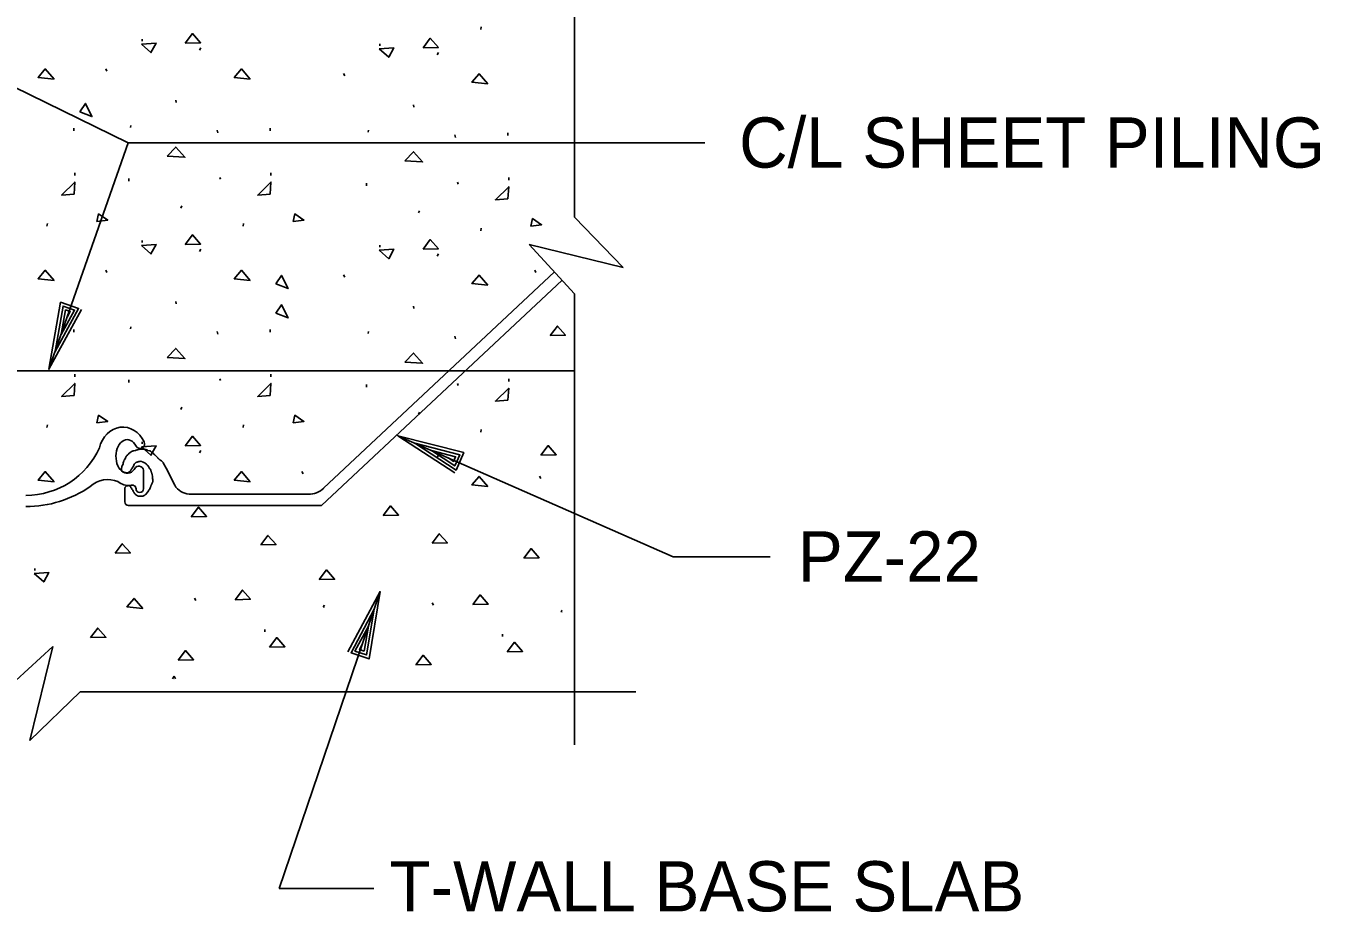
# Model space of a CAD drawing. Extents: x 22369.6 to 22428.3, y 22369.6 to 22415.
# Drawn here: x 22384.482 to 22389.267, y 22374.698 to 22377.975 of the extents above; entities that cross this region are included whole.
import ezdxf

# ---------------------------------------------------------------- set-up
doc = ezdxf.new("R2010")
doc.units = 0
for name, color, linetype in [('Level 1', 7, 'Continuous'), ('Level 2', 7, 'Continuous'), ('Level 4', 7, 'Continuous'), ('Level 8', 7, 'Continuous')]:
    doc.layers.add(name, color=color, linetype=linetype)

msp = doc.modelspace()

# ---------------------------------------------------------------- linework, layer by layer
at = {"layer": 'Level 1'}
for p, q in [((22386.5109, 22377.2675), (22386.5109, 22379.7606)), ((22384.8608, 22377.5434), (22384.0344, 22377.9463)), ((22384.5676, 22376.7059), (22384.8608, 22377.5434)), ((22384.8608, 22377.5434), (22386.9925, 22377.5434)), ((22384.6631, 22377.4226), (22384.6631, 22377.4318)), ((22384.5602, 22377.2348), (22384.5617, 22377.2444)), ((22386.6908, 22377.0817), (22386.5109, 22377.2675)), ((22386.5109, 22376.984), (22386.3432, 22377.1673)), ((22386.3432, 22377.1673), (22386.6908, 22377.0817)), ((22386.5109, 22375.3165), (22386.5109, 22376.984)), ((22384.6597, 22376.8431), (22384.6597, 22376.8531)), ((22384.5904, 22376.771), (22384.5904, 22376.771)), ((22384.5676, 22376.7059), (22384.5676, 22376.7059)), ((22383.6419, 22376.6994), (22386.5109, 22376.6994)), ((22384.6631, 22376.6781), (22384.6631, 22376.6874)), ((22385.9339, 22376.5397), (22385.9376, 22376.5475)), ((22384.9119, 22376.4299), (22384.9126, 22376.4372)), ((22385.857, 22376.46), (22386.8753, 22376.0124)), ((22385.857, 22376.46), (22385.857, 22376.46)), ((22385.9203, 22376.4322), (22385.9203, 22376.4322)), ((22385.1237, 22376.3967), (22385.1286, 22376.405)), ((22386.0024, 22376.3792), (22386.0074, 22376.3875)), ((22385.5072, 22376.3191), (22385.5027, 22376.3279)), ((22386.8753, 22376.0124), (22387.2338, 22376.0124)), ((22385.7919, 22375.8837), (22385.419, 22374.7862)), ((22385.7919, 22375.8837), (22385.7919, 22375.8837)), ((22385.7697, 22375.8182), (22385.7697, 22375.8182)), ((22384.3989, 22375.513), (22384.5822, 22375.6807)), ((22384.5822, 22375.6807), (22384.4967, 22375.3331)), ((22384.4967, 22375.3331), (22384.6824, 22375.513)), ((22386.7371, 22375.513), (22384.6824, 22375.513)), ((22385.419, 22374.7862), (22385.7687, 22374.7862))]:
    msp.add_line(p, q, dxfattribs=at)
msp.add_lwpolyline([(22384.7447, 22377.2522), (22384.785, 22377.2574), (22384.7512, 22377.2801)], close=True, dxfattribs=at)
for points in [[(22384.6884, 22376.9265), (22384.5676, 22376.7059), (22384.6107, 22376.9537), (22384.6771, 22376.9304), (22384.5904, 22376.771), (22384.6198, 22376.9393), (22384.6623, 22376.9244), (22384.6123, 22376.8336), (22384.6288, 22376.9249), (22384.6463, 22376.9187), (22384.6351, 22376.8987)], [(22386.0681, 22376.3222), (22385.857, 22376.46), (22386.1013, 22376.3977), (22386.0729, 22376.3331), (22385.9203, 22376.4322), (22386.0862, 22376.3898), (22386.068, 22376.3484), (22385.9812, 22376.4054), (22386.0711, 22376.3819), (22386.0636, 22376.3648), (22386.0445, 22376.3776)], [(22385.6729, 22375.6614), (22385.7919, 22375.8837), (22385.7509, 22375.6349), (22385.6842, 22375.6576), (22385.7697, 22375.8182), (22385.7418, 22375.6493), (22385.6989, 22375.6638), (22385.7483, 22375.7552), (22385.7326, 22375.6636), (22385.715, 22375.6696), (22385.726, 22375.6897)], [(22386.4644, 22375.8153), (22386.4598, 22375.8098)], [(22386.4598, 22375.8098), (22386.4647, 22375.8093)]]:
    msp.add_lwpolyline(points, dxfattribs=at)
at = {"layer": 'Level 2'}
for p, q in [((22385.5826, 22376.2656), (22386.4365, 22377.0654)), ((22385.5754, 22376.2019), (22386.4645, 22377.0347)), ((22384.917, 22376.3336), (22384.917, 22376.2638)), ((22385.001, 22376.3405), (22385.0323, 22376.2768)), ((22384.8482, 22376.2155), (22384.8481, 22376.2601)), ((22384.8894, 22376.2634), (22384.8894, 22376.2638)), ((22385.5263, 22376.2434), (22385.0859, 22376.2434)), ((22384.8603, 22376.2019), (22385.5754, 22376.2019))]:
    msp.add_line(p, q, dxfattribs=at)
for points in [[(22384.8683, 22376.3287), (22384.8671, 22376.3276), (22384.8645, 22376.3259), (22384.8638, 22376.3259), (22384.8617, 22376.3238), (22384.8599, 22376.3233), (22384.8594, 22376.3228), (22384.8562, 22376.3226), (22384.855, 22376.3226), (22384.8535, 22376.3229), (22384.8526, 22376.3229), (22384.8511, 22376.3233), (22384.8501, 22376.3231), (22384.8492, 22376.3234), (22384.8484, 22376.3236), (22384.8466, 22376.3244), (22384.8444, 22376.3249), (22384.8433, 22376.3254), (22384.8426, 22376.3259), (22384.8418, 22376.3267), (22384.8386, 22376.3286), (22384.8375, 22376.3291), (22384.8371, 22376.3299), (22384.8361, 22376.3307), (22384.8356, 22376.3321), (22384.8355, 22376.3349), (22384.8358, 22376.3382), (22384.836, 22376.3413), (22384.8365, 22376.3427), (22384.8368, 22376.3442), (22384.8373, 22376.3457), (22384.8373, 22376.3475), (22384.8401, 22376.3528), (22384.8413, 22376.3558), (22384.8413, 22376.3568), (22384.8418, 22376.3584), (22384.8419, 22376.3594), (22384.8436, 22376.3634), (22384.8446, 22376.3664), (22384.8461, 22376.3704), (22384.8467, 22376.3712), (22384.8482, 22376.3727), (22384.8501, 22376.3763), (22384.8507, 22376.3783), (22384.8519, 22376.381), (22384.8531, 22376.383), (22384.8534, 22376.3836), (22384.8539, 22376.3848), (22384.8545, 22376.3858), (22384.856, 22376.3871), (22384.8582, 22376.3886), (22384.8589, 22376.3893), (22384.86, 22376.3901), (22384.8607, 22376.3911), (22384.8612, 22376.3914), (22384.8625, 22376.3936), (22384.8645, 22376.3951), (22384.8668, 22376.3961), (22384.8671, 22376.3967), (22384.8731, 22376.401), (22384.8768, 22376.4025), (22384.8784, 22376.4035), (22384.8802, 22376.404), (22384.8817, 22376.4045), (22384.8864, 22376.4053), (22384.8884, 22376.4057), (22384.8905, 22376.4063), (22384.8932, 22376.4077), (22384.8955, 22376.408), (22384.8983, 22376.409), (22384.9006, 22376.409), (22384.9098, 22376.4097), (22384.9121, 22376.4103), (22384.9154, 22376.4105), (22384.9174, 22376.4103), (22384.9202, 22376.4097), (22384.924, 22376.4095), (22384.926, 22376.409), (22384.9287, 22376.4075), (22384.9305, 22376.4068), (22384.9326, 22376.4063), (22384.9335, 22376.4057), (22384.9393, 22376.4039), (22384.9406, 22376.4035), (22384.9431, 22376.4024), (22384.9466, 22376.3996)], [(22384.9466, 22376.3996), (22384.9494, 22376.3976), (22384.9514, 22376.3961), (22384.9526, 22376.3944), (22384.9552, 22376.3924), (22384.9569, 22376.3904), (22384.958, 22376.3898), (22384.9585, 22376.3893), (22384.9607, 22376.3881), (22384.9618, 22376.3868), (22384.9622, 22376.3859), (22384.964, 22376.384), (22384.965, 22376.3825), (22384.9698, 22376.378), (22384.9701, 22376.3765), (22384.9725, 22376.375), (22384.9733, 22376.374), (22384.9774, 22376.3702), (22384.9807, 22376.3684), (22384.9842, 22376.3665), (22384.9849, 22376.3659), (22384.9861, 22376.3646), (22384.9872, 22376.3639), (22384.9889, 22376.3616), (22384.9892, 22376.3607), (22384.9895, 22376.3601), (22384.99, 22376.3591), (22384.99, 22376.3592), (22384.9902, 22376.3594), (22385.001, 22376.3405)], [(22384.9494, 22376.2841), (22384.9499, 22376.2853), (22384.9512, 22376.2913), (22384.9512, 22376.2924), (22384.9512, 22376.2936), (22384.9514, 22376.2952), (22384.9514, 22376.2976), (22384.9504, 22376.3017), (22384.9502, 22376.3032), (22384.9501, 22376.3037), (22384.9504, 22376.3045), (22384.9501, 22376.305), (22384.9504, 22376.3063), (22384.9502, 22376.3075), (22384.9506, 22376.3088), (22384.9502, 22376.3105), (22384.9487, 22376.3153), (22384.9474, 22376.3211), (22384.9471, 22376.3226), (22384.9464, 22376.3238), (22384.9461, 22376.3249), (22384.9461, 22376.3257), (22384.9456, 22376.3267), (22384.9452, 22376.3281), (22384.9451, 22376.3291), (22384.9446, 22376.3301), (22384.9444, 22376.3311), (22384.9436, 22376.3331), (22384.9433, 22376.3344), (22384.9426, 22376.336), (22384.9406, 22376.338), (22384.9393, 22376.3392), (22384.9381, 22376.3417), (22384.9356, 22376.346), (22384.9351, 22376.3471), (22384.9345, 22376.3478), (22384.9328, 22376.3503), (22384.9313, 22376.3516), (22384.9305, 22376.3519), (22384.93, 22376.3528), (22384.9287, 22376.3539), (22384.927, 22376.3561), (22384.9257, 22376.3573), (22384.925, 22376.3578), (22384.9244, 22376.3583), (22384.9237, 22376.3586), (22384.923, 22376.3589), (22384.922, 22376.3592), (22384.9196, 22376.3601), (22384.9181, 22376.3604), (22384.9156, 22376.3619), (22384.9116, 22376.3637), (22384.9106, 22376.3642), (22384.9061, 22376.3652), (22384.9043, 22376.3649), (22384.9031, 22376.3649), (22384.9015, 22376.3644), (22384.9003, 22376.3642), (22384.8993, 22376.3641), (22384.897, 22376.3637), (22384.8963, 22376.3637), (22384.894, 22376.3627), (22384.8927, 22376.3626), (22384.891, 22376.3619), (22384.8899, 22376.3609), (22384.889, 22376.3604), (22384.8879, 22376.3597), (22384.887, 22376.3591), (22384.8864, 22376.3581), (22384.8857, 22376.3578), (22384.8854, 22376.3571), (22384.8844, 22376.3564), (22384.8837, 22376.3558), (22384.8829, 22376.3548), (22384.8812, 22376.3513), (22384.8796, 22376.3475), (22384.8787, 22376.3461), (22384.8773, 22376.3438), (22384.8766, 22376.3423), (22384.8738, 22376.338), (22384.872, 22376.336), (22384.871, 22376.3335), (22384.8706, 22376.3329), (22384.8698, 22376.3319), (22384.8693, 22376.3304), (22384.8683, 22376.3287)], [(22384.8481, 22376.2601), (22384.8486, 22376.2609), (22384.8484, 22376.2624), (22384.8481, 22376.2624), (22384.8481, 22376.2636), (22384.8477, 22376.2654), (22384.8479, 22376.2659), (22384.8479, 22376.2657), (22384.8479, 22376.2664), (22384.8486, 22376.267), (22384.8489, 22376.2679), (22384.8499, 22376.2699), (22384.8499, 22376.2699), (22384.8517, 22376.272), (22384.8521, 22376.2722), (22384.8529, 22376.2732), (22384.8542, 22376.274), (22384.8554, 22376.2745), (22384.8582, 22376.275), (22384.8612, 22376.2753), (22384.8628, 22376.2753), (22384.8643, 22376.275), (22384.8676, 22376.2738), (22384.8685, 22376.2725), (22384.8686, 22376.271), (22384.8698, 22376.2697), (22384.8701, 22376.2684), (22384.8725, 22376.2664), (22384.8726, 22376.2659), (22384.8741, 22376.2626), (22384.8758, 22376.2602), (22384.8776, 22376.2583), (22384.8786, 22376.2551), (22384.8792, 22376.2541), (22384.8804, 22376.2521), (22384.8809, 22376.2515), (22384.8822, 22376.2486), (22384.8826, 22376.2481), (22384.8834, 22376.2476), (22384.8842, 22376.2466), (22384.887, 22376.2442), (22384.8872, 22376.2437), (22384.8879, 22376.243), (22384.8885, 22376.2418), (22384.8892, 22376.241), (22384.891, 22376.2397), (22384.8925, 22376.239), (22384.894, 22376.238), (22384.8962, 22376.2374), (22384.8972, 22376.2369), (22384.8983, 22376.2369), (22384.899, 22376.2365), (22384.9026, 22376.2362), (22384.9045, 22376.236), (22384.9088, 22376.2364), (22384.9098, 22376.2362), (22384.9114, 22376.2362), (22384.9151, 22376.237), (22384.9192, 22376.2387), (22384.92, 22376.2392), (22384.921, 22376.2397), (22384.922, 22376.2403), (22384.9234, 22376.2413), (22384.9245, 22376.242), (22384.9249, 22376.2427), (22384.9267, 22376.2443), (22384.9277, 22376.2457), (22384.9323, 22376.2508), (22384.9333, 22376.2523), (22384.9351, 22376.2556), (22384.9371, 22376.2588), (22384.9378, 22376.2596), (22384.9381, 22376.2606), (22384.939, 22376.2612), (22384.9403, 22376.2637), (22384.9419, 22376.2669), (22384.9429, 22376.269), (22384.9447, 22376.2743), (22384.9447, 22376.275), (22384.9452, 22376.2758), (22384.9456, 22376.2768), (22384.9461, 22376.2777), (22384.9472, 22376.2811), (22384.9479, 22376.2825), (22384.9494, 22376.2841)]]:
    msp.add_lwpolyline(points, dxfattribs=at)
for centre, radius, start, end in [((22384.9042, 22376.4298), 0.0171, 210.0864, 24.1441), ((22384.4823, 22376.5371), 0.2977, 270, 335.9098), ((22384.9001, 22376.3302), 0.0172, 348.5103, 135.7394), ((22384.7851, 22376.2049), 0.0931, 66.293, 134.0783), ((22384.863, 22376.3391), 0.0635, 230.4241, 276.2781), ((22384.8756, 22376.2634), 0.0138, 0.0038, 114.2261), ((22385.0932, 22376.3147), 0.0717, 211.905, 264.1589), ((22384.4823, 22376.6177), 0.4198, 270, 304.5362), ((22384.9032, 22376.2638), 0.0138, 180, 0), ((22385.5263, 22376.3263), 0.0829, 270, 313.4699), ((22384.8621, 22376.2156), 0.0138, 180.2909, 270.0528)]:
    msp.add_arc(centre, radius, start, end, dxfattribs=at)
for centre, major_axis, ratio, start_param, end_param in [((22384.8406, 22376.388), (0, 0.1036), 0.866676, 5.202938, 7.584426), ((22384.8566, 22376.3832), (0, 0.0622), 0.666679, 5.371054, 10.276478)]:
    msp.add_ellipse(centre, major_axis=major_axis, ratio=ratio, start_param=start_param, end_param=end_param, dxfattribs=at)
at = {"layer": 'Level 8'}
for p, q in [((22386.1641, 22377.9618), (22386.1656, 22377.9714)), ((22384.9119, 22377.9187), (22384.9126, 22377.926)), ((22385.7907, 22377.9012), (22385.7913, 22377.9085)), ((22385.1237, 22377.8856), (22385.1286, 22377.8939)), ((22386.0024, 22377.8681), (22386.0074, 22377.8764)), ((22384.782, 22377.808), (22384.7776, 22377.8167)), ((22385.6608, 22377.7905), (22385.6564, 22377.7992)), ((22385.0374, 22377.6924), (22385.0368, 22377.7005)), ((22385.9162, 22377.6749), (22385.9156, 22377.683)), ((22384.6597, 22377.5876), (22384.6597, 22377.5975)), ((22384.8688, 22377.5993), (22384.8701, 22377.6068)), ((22385.1918, 22377.5796), (22385.189, 22377.5895)), ((22385.3849, 22377.5876), (22385.3849, 22377.5975)), ((22385.7476, 22377.5818), (22385.7489, 22377.5893)), ((22386.0706, 22377.5621), (22386.0678, 22377.5721)), ((22386.2636, 22377.5701), (22386.2636, 22377.58)), ((22385.3883, 22377.4226), (22385.3883, 22377.4318)), ((22384.8626, 22377.4012), (22384.8626, 22377.4111)), ((22385.2018, 22377.408), (22385.1989, 22377.4151)), ((22385.7414, 22377.3837), (22385.7414, 22377.3936)), ((22386.0806, 22377.3905), (22386.0777, 22377.3976)), ((22386.2671, 22377.4051), (22386.2671, 22377.4143)), ((22385.0552, 22377.3017), (22385.0588, 22377.3095)), ((22385.9339, 22377.2842), (22385.9376, 22377.292)), ((22385.2854, 22377.2348), (22385.2868, 22377.2444)), ((22384.9119, 22377.1743), (22384.9126, 22377.1816)), ((22386.1641, 22377.2173), (22386.1656, 22377.227)), ((22385.1237, 22377.1411), (22385.1286, 22377.1494)), ((22385.7907, 22377.1568), (22385.7913, 22377.1641)), ((22386.0024, 22377.1236), (22386.0074, 22377.1319)), ((22384.782, 22377.0635), (22384.7776, 22377.0723)), ((22385.6608, 22377.046), (22385.6564, 22377.0548)), ((22386.3677, 22377.0635), (22386.3632, 22377.0723)), ((22385.0374, 22376.9479), (22385.0368, 22376.9561)), ((22385.9162, 22376.9304), (22385.9156, 22376.9386)), ((22384.8688, 22376.8549), (22384.8701, 22376.8624)), ((22385.3849, 22376.8431), (22385.3849, 22376.8531)), ((22385.1918, 22376.8352), (22385.189, 22376.8451)), ((22385.7476, 22376.8374), (22385.7489, 22376.8449)), ((22386.0706, 22376.8177), (22386.0678, 22376.8276)), ((22384.8626, 22376.6567), (22384.8626, 22376.6667)), ((22385.2018, 22376.6635), (22385.1989, 22376.6707)), ((22385.3883, 22376.6781), (22385.3883, 22376.6874)), ((22386.2671, 22376.6606), (22386.2671, 22376.6699)), ((22385.7414, 22376.6392), (22385.7414, 22376.6492)), ((22386.0806, 22376.646), (22386.0777, 22376.6532)), ((22385.0552, 22376.5572), (22385.0588, 22376.565)), ((22384.5602, 22376.4904), (22384.5617, 22376.5)), ((22385.2854, 22376.4904), (22385.2868, 22376.5)), ((22386.1641, 22376.4729), (22386.1656, 22376.4825)), ((22386.386, 22376.3016), (22386.3815, 22376.3104)), ((22384.5152, 22375.9615), (22384.5158, 22375.9688)), ((22385.1105, 22375.8507), (22385.106, 22375.8595)), ((22385.9893, 22375.8332), (22385.9848, 22375.842)), ((22385.3659, 22375.7351), (22385.3652, 22375.7432)), ((22386.2447, 22375.7176), (22386.244, 22375.7257))]:
    msp.add_line(p, q, dxfattribs=at)
for points in [[(22385.0716, 22377.9118), (22385.0983, 22377.9471), (22385.1283, 22377.9131)], [(22384.9094, 22377.908), (22384.9447, 22377.8764), (22384.9636, 22377.9118)], [(22385.9504, 22377.8943), (22385.9771, 22377.9296), (22386.0071, 22377.8956)], [(22385.7882, 22377.8905), (22385.8235, 22377.859), (22385.8424, 22377.8943)], [(22384.5865, 22377.7781), (22384.5537, 22377.8159), (22384.5273, 22377.7846)], [(22385.3117, 22377.7781), (22385.2789, 22377.8159), (22385.2525, 22377.7846)], [(22386.1905, 22377.7606), (22386.1577, 22377.7984), (22386.1313, 22377.7671)], [(22384.6812, 22377.6572), (22384.7265, 22377.6396), (22384.7026, 22377.6886)], [(22385.0049, 22377.4932), (22385.0364, 22377.5274), (22385.0703, 22377.4895)], [(22385.8837, 22377.4757), (22385.9152, 22377.5099), (22385.9491, 22377.4721)], [(22384.6607, 22377.3534), (22384.6631, 22377.3977), (22384.6141, 22377.3498)], [(22385.3858, 22377.3534), (22385.3883, 22377.3977), (22385.3392, 22377.3498)], [(22386.2646, 22377.3359), (22386.2671, 22377.3802), (22386.218, 22377.3323)], [(22385.4699, 22377.2522), (22385.5102, 22377.2574), (22385.4764, 22377.2801)], [(22386.3487, 22377.2347), (22386.389, 22377.2399), (22386.3552, 22377.2626)], [(22385.0716, 22377.1673), (22385.0983, 22377.2027), (22385.1283, 22377.1687)], [(22385.9504, 22377.1498), (22385.9771, 22377.1852), (22386.0071, 22377.1512)], [(22384.9094, 22377.1635), (22384.9447, 22377.132), (22384.9636, 22377.1673)], [(22385.7882, 22377.146), (22385.8235, 22377.1145), (22385.8424, 22377.1498)], [(22384.5865, 22377.0337), (22384.5537, 22377.0715), (22384.5273, 22377.0401)], [(22385.3117, 22377.0337), (22385.2789, 22377.0715), (22385.2525, 22377.0401)], [(22385.4064, 22377.0215), (22385.4517, 22377.0039), (22385.4278, 22377.0528)], [(22386.1905, 22377.0162), (22386.1577, 22377.054), (22386.1313, 22377.0226)], [(22385.4064, 22376.9128), (22385.4517, 22376.8952), (22385.4278, 22376.9441)], [(22386.4203, 22376.83), (22386.447, 22376.8653), (22386.477, 22376.8313)], [(22385.0049, 22376.7488), (22385.0364, 22376.7829), (22385.0703, 22376.7451)], [(22385.8837, 22376.7313), (22385.9152, 22376.7654), (22385.9491, 22376.7276)], [(22384.6607, 22376.609), (22384.6631, 22376.6532), (22384.6141, 22376.6053)], [(22385.3858, 22376.609), (22385.3883, 22376.6532), (22385.3392, 22376.6053)], [(22386.2646, 22376.5915), (22386.2671, 22376.6357), (22386.218, 22376.5878)], [(22384.7447, 22376.5078), (22384.785, 22376.5129), (22384.7512, 22376.5357)], [(22385.4699, 22376.5078), (22385.5102, 22376.5129), (22385.4764, 22376.5357)], [(22384.9094, 22376.4191), (22384.9447, 22376.3876), (22384.9636, 22376.4229)], [(22385.0716, 22376.4229), (22385.0983, 22376.4582), (22385.1283, 22376.4242)], [(22386.3865, 22376.388), (22386.4132, 22376.4233), (22386.4432, 22376.3893)], [(22384.5865, 22376.2892), (22384.5537, 22376.327), (22384.5273, 22376.2957)], [(22385.3117, 22376.2892), (22385.2789, 22376.327), (22385.2525, 22376.2957)], [(22386.1905, 22376.2717), (22386.1577, 22376.3095), (22386.1313, 22376.2782)], [(22385.0937, 22376.1605), (22385.1203, 22376.1958), (22385.1504, 22376.1618)], [(22385.8034, 22376.1649), (22385.8301, 22376.2002), (22385.8601, 22376.1662)], [(22385.3505, 22376.056), (22385.3772, 22376.0914), (22385.4072, 22376.0574)], [(22385.9839, 22376.0622), (22386.0106, 22376.0975), (22386.0406, 22376.0635)], [(22384.8118, 22376.0254), (22384.8385, 22376.0607), (22384.8685, 22376.0267)], [(22386.3231, 22376.0073), (22386.3498, 22376.0426), (22386.3798, 22376.0086)], [(22384.5127, 22375.9507), (22384.548, 22375.9192), (22384.5669, 22375.9545)], [(22385.5669, 22375.9282), (22385.5936, 22375.9635), (22385.6237, 22375.9295)], [(22384.915, 22375.8208), (22384.8822, 22375.8586), (22384.8558, 22375.8273)], [(22385.2558, 22375.8537), (22385.2825, 22375.889), (22385.3125, 22375.855)], [(22386.1346, 22375.8362), (22386.1613, 22375.8715), (22386.1913, 22375.8375)], [(22384.7212, 22375.7135), (22384.7479, 22375.7488), (22384.7779, 22375.7148)], [(22385.3829, 22375.6784), (22385.4096, 22375.7137), (22385.4396, 22375.6797)], [(22385.0454, 22375.6302), (22385.0721, 22375.6655), (22385.1022, 22375.6315)], [(22386.2617, 22375.6609), (22386.2884, 22375.6962), (22386.3184, 22375.6622)], [(22385.9242, 22375.6127), (22385.9509, 22375.648), (22385.9809, 22375.614)]]:
    msp.add_lwpolyline(points, close=True, dxfattribs=at)
for points in [[(22385.5856, 22375.8328), (22385.581, 22375.8273)], [(22385.581, 22375.8273), (22385.586, 22375.8268)], [(22385.0306, 22375.5711), (22385.0239, 22375.5613)], [(22385.0355, 22375.5612), (22385.0306, 22375.5711)]]:
    msp.add_lwpolyline(points, dxfattribs=at)

# ---------------------------------------------------------------- texts
at = {"layer": 'Level 4'}
for s, height, p in [('C/L SHEET PILING', 0.185698, (22387.119, 22377.4511)), ('PZ-22', 0.1857, (22387.3365, 22375.9208)), ('T-WALL BASE SLAB', 0.185698, (22385.827, 22374.7011))]:
    msp.add_text(s, height=height, dxfattribs=at).set_placement(p)

doc.saveas('drawing.dxf')
